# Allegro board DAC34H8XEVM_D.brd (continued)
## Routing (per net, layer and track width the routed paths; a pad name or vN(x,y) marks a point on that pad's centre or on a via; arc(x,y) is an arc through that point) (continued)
N26793352: length 1
  BOTTOM w0.152: R43.2 C34.1
N26794794: length 2
  BOTTOM w0.152: R43.1 C35.1 R133.1
N26951427: length 5.3
  TOP w0.305: T2.4 91.44,60.83 86.36,60.83
N26951636: length 5.3
  TOP w0.305: T9.4 91.44,55.75 T2.6
N26951698: length 5.5
  TOP w0.305: R106.1 R21.2 R22.1 74.37,57.02 73.41,57.99 C265.1 C262.2 L32.1
N26961459: length 5.1
  TOP w0.305: T10.6 91.31,78.74 T3.4
N26961634: length 5.6
  TOP w0.305: R32.2 R34.2
N26961668: length 5.2
  TOP w0.305: R28.1 91.19,73.66 T10.4
N26961730: length 5.6
  TOP w0.305: L35.1 C271.2 C274.1 73.41,75.72 74.32,74.8 R30.1 R29.2 R108.1
N26965899: length 5.6
  TOP w0.305: R110.1 R37.2 R38.1 74.32,87.63 73.41,88.54 C283.1 C280.2 L39.1
N27066000: length 1
  BOTTOM w0.152: R44.2 R45.1
N27118781: length 5.6
  TOP w0.305: L33.1 C265.2 73.41,59.16 74.32,60.07 R100.2 R23.1 R107.1
N27125590: length 5.6
  TOP w0.305: R109.1 R101.2 74.32,77.85 73.41,76.94 C274.2 C277.1 L38.1
N27129848: length 5.6
  TOP w0.305: R111.1 R39.1 R102.2 74.32,90.68 73.41,89.76 C283.2 C286.1 L42.1
N27288441: length 2.6
  BOTTOM w0.152: U3.2 96.45,114.79 R79.2
N27288443: length 24.9
  TOP w0.381: v2(103.61,103.78) 103.84,103.78 105.41,105.36 105.41,111.2 113.14,118.94 v2(113.65,118.94)
  TOP w0.508: J14.2 v2(113.65,118.94)
  BOTTOM w0.381: U3.16 v2(103.61,103.78)
  BOTTOM w0.508: C95.1 111.7,118.94 v2(113.65,118.94)
N27288450: length 16.2
  BOTTOM w0.381: U3.20 101,108.8 102.97,110.77 C92.1
  BOTTOM w0.508: FB14.1 108.64,112.56 C93.1 108.57,110.78 C92.1
N27288471: length 2.8
  BOTTOM w0.152: R80.2 101,114.26 U3.9
N27288510: length 3
  BOTTOM w0.152: U3.10 101.65,113.89 R81.2
N27288614: length 11.9
  TOP w0.152: v2(98.27,114.35) 98.27,114.25 102.95,109.58 v2(102.95,109.47)
  BOTTOM w0.152: v2(102.95,109.47) 102.95,105.22 U3.17 ; v2(98.27,114.35) 98.27,114.55 98.68,114.96 C97.1
N27288630: length 23.1
  TOP w0.381: v2(104.6,106.32) 104.6,112.24 112.04,119.68 113.56,119.68 v2(113.61,119.74)
  TOP w0.508: J14.3 v2(113.61,119.74)
  BOTTOM w0.381: v2(104.6,106.32) 104.25,105.98 U3.15
  BOTTOM w0.508: v2(113.61,119.74) 111.79,119.74 C96.1
N27288689: length 18.7
  TOP w0.152: v2(95.63,116.66) 95.38,116.41 94.39,116.41 94.08,116.71 94.08,117.98 94.74,118.64 95.81,118.64 v2(96.91,119.75) 96.91,119.8 97.16,120.04 97.16,121.26 98.45,122.56 98.7,122.56 100.07,123.92 v2(100.07,128.01)
  BOTTOM w0.152: U4.8 v2(96.91,119.75) ; R75.1 v2(95.63,116.66) ; U9.2 v2(100.07,128.01)
N27288797: length 2.6
  BOTTOM w0.152: R75.2 95.8,114.82 U3.1
N27288876: length 3.1
  BOTTOM w0.152: U3.5 98.4,113.69 R76.2
N27289021: length 2.8
  BOTTOM w0.152: U3.3 97.1,114.42 R77.2
N27289053: length 3.2
  BOTTOM w0.152: R82.2 99.16,113.44 99.16,112.58 U3.6
N27299600: length 3.9
  BOTTOM w0.152: R78.1 104.5,116.74 104.5,118.67 104.32,118.85 U5.9
N27358249: length 5.1
  TOP w0.305: T8.6 T1.4
N27358251: length 5.6
  TOP w0.305: R16.2 R13.2
N27379986: length 5.1
  TOP w0.305: T11.6 91.31,91.69 T4.4
N27396936: length 5.2
  TOP w0.305: R4.1 91.19,43.18 T8.4
N27404153: length 5.1
  TOP w0.305: T4.6 91.31,86.61 T11.4
N27685853: length 1
  TOP w0.305: R99.1 R7.2
N27688076: length 1
  TOP w0.305: 74.42,59.05 R22.2
N27690605: length 1
  TOP w0.305: R101.1 R30.2
N27692844: length 1
  TOP w0.305: R102.1 R38.2
N27760065: length 8.1
  TOP w0.305: U2.29 v2(67.58,112.18) ; v2(67.67,110.06) 67.67,110.21 67.19,110.68 U2.26 ; C76.1 68.25,110.62 v2(68.2,110.67) ; v2(67.46,113.67) 67.44,113.68 U2.32 ; C77.1 v2(68.19,113.67) ; C78.1 v2(68.2,112.29)
  BOTTOM w0.508: FB9.2 v2(68.25,109.88) ; C81.1 67.18,108.79 v2(67.67,109.27) ; v2(67.67,110.06) C79.1 ; C80.1 67.44,111.43 v2(68.2,110.67)
N27760104: length 5.6
  TOP w0.305: U2.47 60.71,117.05 60.49,117.27 60.38,117.27 60.12,117.53 v2(59.97,117.53) 59.6,117.89 C65.1
  BOTTOM w0.508: C66.1 60.55,117.53 v2(59.97,117.53) 59.94,117.55 v2(59.94,118.16) 59.56,118.16 59.05,118.67 FB5.2
N27760106: length 4.7
  TOP w0.152: C64.2 66.62,118.49 65.28,117.14 65.28,116.53 U2.38
N27760178: length 5.2
  TOP w0.508: C180.1 FB25.2 57.02,136.88 59.64,134.26 JP7.1
N27760241: length 4.1
  TOP w0.381: C177.1 R95.1 54.48,123.54 U17.5
N27760265: length 7
  TOP w0.305: J9.1 R49.2 C53.1
N27760429: length 9.8
  TOP w0.152: C75.2 50.95,116.99 51.5,116.45 51.99,116.45 52.67,115.77 54.1,115.77 55.17,114.71 56.07,114.71 56.1,114.73 57.79,114.73 58.33,114.18 U2.4
N27760435: length 4.2
  TOP w0.152: JP4.3 63.14,132.08 R51.2 63.2,132.97 R103.2
N27760437: length 4.3
  TOP w0.305: C86.1 57.69,112.17 v2(57.71,112.19) 57.73,112.17 58.29,112.17 58.27,112.19 58.36,112.19 58.37,112.18 U2.8
  BOTTOM w0.508: C87.1 57.73,112.17 FB12.2 57.3,111.79 v2(57.71,112.19)
N27760441: length 19.5
  TOP w0.152: U2.31 69.81,113.18 70.1,113.48 70.1,115.49 71.2,116.59 71.2,125.78 JP5.2
N27760496: length 4
  TOP w0.305: U2.21 v2(64.21,107.83) C82.1
  BOTTOM w0.508: C83.1 64.21,107.83 v2(64.21,107.83) 64.57,107.47 FB10.2
N27760516: length 3.5
  TOP w0.305: U2.1 58.61,115.68 v2(58.57,115.65) 58.27,115.65 58.19,115.72 v2(57.71,115.72) 57.7,115.73 C73.1
  BOTTOM w0.508: C74.1 v2(58.57,115.65) ; v2(57.71,115.72) 57.71,115.67 57.35,115.32 FB8.2
N27760568: length 10.2
  TOP w0.152: U2.9 59.31,111.56 56.11,111.56 55.68,111.13 54.81,110.26 54.81,109.4 53.98,108.56 53.62,108.56 R61.2
  TOP w0.305: R116.1 R65.1 R61.2
N27760578: length 7.7
  TOP w0.305: C177.2 R167.2 ; R166.2 55.62,115.19 58.12,115.19 58.62,114.68 U2.3
  TOP w0.381: R166.2 R167.2
N27760635: length 11.5
  TOP w0.508: v2(47.42,130) 46.25,131.17 U17.1 46.09,135.22 TP14.1 46.81,135.61 47.96,134.47 R164.2 R165.1
  BOTTOM w0.508: U16.8 48.08,129.34 v2(47.42,130)
N27760767: length 10.2
  TOP w0.152: R60.2 53.54,108.28 54.09,108.28 55.09,109.28 55.09,110.15 55.96,111.01 56.22,111.28 59.34,111.28 U2.10
  TOP w0.305: R117.1 R64.1 R60.2
N27760883: length 4.3
  TOP w0.152: R55.2 70.47,112.75 66.55,112.75 U2.30
N27760967: length 1.2
  TOP w0.152: R48.2 63.58,121.88 C52.2
N27760969: length 20.6
  TOP w0.152: U2.12 v2(59.43,109.63)
  L6_PWR w0.152: v2(59.43,109.63) 59.43,116.84 56.58,119.7 56.58,126.48 JP6.2
N27760997: length 4
  TOP w0.305: C67.1 v2(57.66,114.05) 58.03,113.68 U2.5
  BOTTOM w0.508: C68.1 58,113.72 v2(57.66,114.05) 57.3,113.7 FB6.2
N27761158: length 3.6
  TOP w0.305: U2.18 62.71,107.98 v2(62.71,107.98) 62.43,107.7 C88.1
  BOTTOM w0.508: C89.1 62.69,108 v2(62.71,107.98) 62.71,107.94 62.83,107.83 FB13.1
N27761194: length 1.8
  TOP w0.305: R52.2 69.29,121.31 D1.1
N27761235: length 4.8
  TOP w0.152: U2.37 65.71,116.86 68.02,119.18 R52.1
N27761514: length 5.3
  TOP w0.152: R54.2 54.78,113.33 55.42,113.33 55.63,113.13 56.59,113.13 56.64,113.08 59.33,113.08 U2.6
N27761516: length 5.3
  TOP w0.152: U2.7 59.34,112.78 56.55,112.78 56.48,112.85 55.47,112.85 55.27,113.06 54.8,113.06 R58.2
N27761629: length 3.4
  TOP w0.152: C63.2 58.04,118.47 58.04,118.21 59.79,116.46 U2.48
N27761758: length 3.4
  TOP w0.305: v2(58.37,109.98) 58.37,110.39 58.66,110.68 U2.11 ; v2(57.81,110.19) 57.48,110.52 C84.1
  BOTTOM w0.508: C85.1 v2(57.94,110.72) ; v2(57.3,109.6) FB11.2
N27792689: length 1
  TOP w0.152: C1.2 R149.2
N27792693: length 1
  TOP w0.152: C2.2 R152.2
N27795123: length 1
  TOP w0.152: R125.2 C4.2
N27795145: length 1
  TOP w0.152: R154.2 C3.2
N27836250: length 13
  BOTTOM w1.524: TP12.1 38.07,13.46 JP10.1
  BOTTOM w2.032: 38.07,14.61 46.41,14.61 J18.1
N27836254: length 2.5
  TOP w0.254: D2.1 42.65,27.56 v2(42.65,26.54)
  BOTTOM w0.254: R143.1 v2(42.65,26.54)
N27959634: length 4.9
  TOP w0.305: U11.4 52.84,19.95 52.45,19.56 52.45,17.81 R148.2
  TOP w0.508: 51.56,8.89 FB31.1 ; R148.2 C165.1
  TOP w0.762: C165.1 52.43,15.91 52.48,15.91
N27964126: length 7.3
  TOP w0.305: L25.1 56.26,13.23 56.26,14.48 56.87,15.08 56.87,19.23 56.65,19.45 U11.6
N27965290: length 2.7
  TOP w0.305: U11.5 53.34,17.88 R148.1
  TOP w0.508: R148.1 R151.2
N27972790: length 8.2
  TOP w0.508: R150.2 C166.1 53.44,26.42 C167.1
  TOP w1.016: C167.1 L26.2 57.51,26.04 57.89,26.42 57.89,27.18 FB30.1
N27972794: length 8.6
  TOP w0.305: U11.1 53.34,23.98 52.43,24.89 C166.2 R150.1 R153.2
N28017911: length 2.5
  TOP w0.508: U12.5 64.74,10.26 64.97,10.03 C162.1
N28017929: length 6.5
  TOP w0.762: R147.1 C145.1 63.47,7.49 63.47,7.52 ; C164.1 63.47,7.52 ; 63.47,7.52 U12.4
N28017933: length 9
  TOP w0.762: 59.66,7.37 U12.1 ; U12.2 60.93,8 60.17,7.24
  TOP w1.016: 60.17,7.24 60.05,7.37 R146.2
N28058738: length 11
  TOP w0.305: U13.3 v2(70.53,5.42) ; U13.1 v2(70.53,7.7)
  TOP w0.508: v2(52.68,5.33) C133.1 v2(53.57,4.57) ; C169.1 v2(69.16,5.18) ; v2(58.14,4.6) R146.1 v2(57.25,5.33) ; v2(56.36,4.6) R145.2 v2(55.47,5.33) ; v2(51.41,4.5) FB31.3 v2(50.39,5.33) ; v2(54.97,5.08) C234.1 v2(54.46,5.59) ; v2(73.91,3.56) R126.2 v2(74.65,2.69)
N29123763: length 1.9
  TOP w0.508: T1.5 v2(90.3,45.72)
  BOTTOM w0.508: R9.1 90.27,45.75 v2(90.3,45.72)
N29143306: length 2.1
  TOP w0.508: T2.5 v2(90.25,58.42)
  BOTTOM w0.508: R12.1 90.22,58.45 v2(90.25,58.42)
N29165572: length 2.1
  TOP w0.508: T3.5 v2(90.14,76.33)
  BOTTOM w0.508: R14.1 90.12,76.3 v2(90.14,76.33)
N29179841: length 2.1
  TOP w0.508: T4.5 v2(90.17,89.28)
  BOTTOM w0.508: R18.1 90.14,89.26 v2(90.17,89.28)
N29448574: length 5.6
  TOP w0.305: R40.1 R36.2
N29464199: length 5.6
  TOP w0.305: R20.2 R24.1
N29945616: length 5.4
  BOTTOM w0.102: U1.D12 48.98,70.24 49.36,70.62 49.89,70.62 50.12,70.85 50.12,73.08
  BOTTOM w0.152: R133.2 51.26,73.86 50.88,73.86 50.12,73.11 50.12,73.08
N30016149: length 7
  TOP w0.305: 77.52,5.84 77.44,5.84 77.22,5.61 76.99,5.61 ; 77.52,5.84 77.52,6.78 77.74,7 U22.1 ; 77.52,5.84 77.65,5.84 77.65,5.7 ; 77.65,5.7 U22.3 ; 77.65,5.7 77.58,5.7 77.32,5.44 76.99,5.44 76.99,5.61 ; 76.99,5.61 76.81,5.61 76.68,5.49 C240.1
  TOP w1.016: C240.1 R126.1
N30175128: length 15.9
  TOP w0.508: 74.14,9.78 74.27,9.65 R257.2 73.2,8 72.43,7.22 U13.5 ; FB34.1 70.74,14.77 ; C244.1 70.59,11.46 C245.1 70.74,12.6
  TOP w0.762: C146.1 70.74,9.88 C244.1 70.74,14.77
  TOP w1.016: C146.1 R128.2
N30185572: length 13.1
  TOP w0.508: 80.85,7.72 80.11,8.46 80.11,9.27 C149.1 80.37,9.04 ; 80.85,7.72 81.33,7.72 ; 80.85,7.72 80.71,7.72 80.43,7.44 U22.5 ; 81.69,7.72 80.37,9.04 ; 81.69,7.72 R221.2 ; 81.69,7.72 81.33,7.72 ; 80.37,9.04 80.37,8.69 81.33,7.72 ; C246.1 80.11,11.2 C247.1 80.11,13.34 R127.1
  TOP w0.762: C246.1 80.26,9.63 C149.1
N30679143: length 4.9
  BOTTOM w0.508: 114.17,109.96 U20.5 ; 114.17,109.96 113.66,110.46 v2(113.66,111.05) ; 114.17,109.96 114.05,109.83 v2(113.11,109.83) 112.52,109.83 C138.1 ; R134.1 v2(111.07,107.34) ; R135.2 v2(111.38,110.24)
N30742942: length 2.6
  BOTTOM w0.508: JP11.1 108.08,108.05 R137.2
N30744213: length 2
  BOTTOM w0.508: R136.2 JP11.3
N30812023: length 10.9
  TOP w0.152: v2(100.72,122.18) 100.72,121.3 98.25,118.82 v2(97.71,118.82) 97.71,118.31 99.47,116.56 v2(99.69,116.56)
  BOTTOM w0.152: R76.1 v2(99.69,116.56) ; U9.12 v2(100.72,122.18) ; v2(97.71,118.82) 97.69,118.85 U4.9
N30837851: length 2.1
  BOTTOM w0.152: R85.1 93.71,119.25 U4.5
N30839067: length 1.8
  BOTTOM w0.152: U4.4 R138.1
N30879489: length 2
  BOTTOM w0.152: U5.5 100.56,119.25 R139.1
N30880109: length 1.7
  BOTTOM w0.152: U5.4 R140.1
N30892277: length 5.2
  BOTTOM w0.152: U9.3 100.72,130.37 100.46,130.63 98.91,130.63 R84.1
N30900342: length 20.2
  TOP w0.152: v2(100.89,127.27) 100.89,125.22 102.49,123.62 102.79,123.62 103.86,122.56 103.86,119.51 101.73,117.37 v2(101.73,116.56)
  BOTTOM w0.152: R80.1 v2(101.73,116.56) ; U9.5 102.02,127.8 101.49,127.27 v2(100.89,127.27) 98.36,127.27 97.51,128.12 R74.2
N30908653: length 7.3
  BOTTOM w0.152: R86.1 97.79,126.72 101.68,126.72 102.67,127.72 U9.6
N30910378: length 18.2
  TOP w0.152: v2(99.9,122.15) 99.72,122.15 97.46,119.89 97.46,119.61 96.98,119.13 95.94,118.08 95.94,117.37 v2(96.65,116.66)
  BOTTOM w0.152: R79.1 v2(96.65,116.66) ; v2(99.9,122.15) 100.07,122.32 U9.13 100.07,124.79 99.79,125.07 R83.2 96.93,125.55 96.93,126.44 96.75,126.62 95.15,126.62 94.73,127.04 U10.1
N30914286: length 8.9
  TOP w0.152: v2(103.32,122.37) 103.07,122.12 102.62,122.12 101.65,121.16 101.65,119.28 100.71,118.34 v2(100.71,116.56)
  BOTTOM w0.152: R82.1 v2(100.71,116.56) ; U9.8 v2(103.32,122.37)
N30924628: length 9.9
  BOTTOM w0.152: JP13.2 93.68,131.78 93.68,128.04 93.17,127.53 93.17,126.67 93.75,126.09 U10.2 R87.2
N30955591: length 16.3
  BOTTOM w0.152: R81.1 102.49,116.26 102.49,116.48 102.21,116.76 102.21,116.76 101.24,117.73 100.18,117.73 99.44,118.47 99.44,121.28 98.07,122.66 94.92,122.66 92.44,125.14 U10.4
N30963273: length 12.9
  BOTTOM w0.152: R77.1 97.66,115.93 98.09,115.49 104.34,115.49 105.41,116.56 R73.2 105.39,119.25 U5.8
N30997791: length 4.8
  BOTTOM w0.152: JP9.2 96.39,129.41 R84.2
N30998469: length 6.7
  BOTTOM w0.152: R86.2 95.91,127.1 95.17,127.84 95.17,131.5 JP12.2
N31553936: length 5.5
  BOTTOM w0.152: R87.1 99.62,126.09 101.37,124.33 U9.11
N32018373: length 10
  BOTTOM w0.152: JP8.2 103.99,131.6 103.99,127.51 102.67,126.19 U9.9
N33970284: length 3
  TOP w0.508: U22.4 82.41,5.7 R315.2 R221.1
N33977043: length 2.9
  TOP w0.508: U13.4 74.13,5.83 R316.2 R257.1
N34116776: length 2
  TOP w0.305: C116.1 16.26,106.37 U15.6
N34116835: length 3.2
  TOP w0.305: U15.3 22.76,106.37 22.96,106.17 R170.1 R168.2
N34123238: length 16.1
  TOP w1.016: 76.56,13.59 76.89,13.92 76.89,14.61 ; 76.56,13.59 77.9,13.59 ; 76.56,13.59 76.17,13.97 ; 76.56,13.59 74.78,11.81 74.63,11.96 74.63,12.42 76.17,13.97 ; 76.89,14.61 77.9,13.59 ; 76.89,14.61 76.89,15.35 FB35.1 78.33,14.52 R127.2 77.9,13.59 ; 76.17,16.08 76.17,13.97
N34173216: length 3.8
  TOP w0.305: R105.2 79.88,47.24 T8.1
N34173251: length 3.8
  TOP w0.305: R104.2 79.88,44.2 T8.3
N34173344: length 5.6
  TOP w0.305: L30.1 C259.1 C254.2 73.41,46.41 74.24,47.24 R99.2 R10.1 R105.1
N34173621: length 3.6
  TOP w0.305: 80.77,60.83 80.49,60.83 79.73,60.07 R107.2
N34173656: length 3.8
  TOP w0.305: R106.2 79.27,57.02 80.54,55.75 T9.3
N34174309: length 3.7
  TOP w0.305: T10.1 80.47,78.74 79.58,77.85 R109.2
N34174344: length 3.8
  TOP w0.305: T10.3 80.49,73.66 79.35,74.8 R108.2
N34174546: length 3.7
  TOP w0.305: T11.1 80.54,91.69 79.53,90.68 R111.2
N34174581: length 3.7
  TOP w0.305: T11.3 80.52,86.61 79.5,87.63 R110.2
N34195362: length 2
  TOP w0.305: R131.1 48.67,93.03 U6.19
N34195366: length 4.6
  TOP w0.305: C100.2 51.2,100.25 R206.1 51.07,98.65 49.3,98.65 U6.3
N34195397: length 3.1
  TOP w0.305: R207.1 49.78,100.22 v2(50.13,99.87) 50.48,99.52 R206.2 R207.1
  BOTTOM w0.305: C54.2 v2(50.13,99.87) 49.77,100.23
N34195475: length 4.6
  TOP w0.305: C99.2 49.1,100.99 R207.2 48.92,100.82 48.92,98.98 48.17,98.23 U6.4
N34209596: length 19.7
  TOP w0.305: R122.1 44.7,79.43 43.42,80.71 42.68,80.71 42.4,80.99 42.4,81.36 42.77,81.73 42.77,82.1 42.49,82.37 42.12,82.37 41.75,82.01 41.39,82.01 41.11,82.29 41.11,82.65 41.48,83.02 41.48,83.39 41.2,83.67 40.83,83.67 40.46,83.3 40.09,83.3 39.81,83.58 39.81,83.95 40.18,84.32 40.18,84.68 39.9,84.96 39.54,84.96 39.17,84.59 38.8,84.59 38.18,85.22 38.18,89.79 J20.1
N34209604: length 19.6
  TOP w0.305: R123.1 47.75,79.2 47.19,79.76 47.19,80.16 47.62,80.59 48.26,80.59 50.42,82.75 50.42,83.36 49.94,83.85 49.38,83.85 47.04,81.51 46.41,81.51 45.31,82.6 45.31,83.74 45.62,84.05 46,84.05 46.23,83.82 46.23,83.13 46.58,82.78 47.07,82.78 47.85,83.57 J21.1
N34210478: length 19.6
  TOP w0.305: J22.1 55.83,93.37 55.25,92.79 53.42,92.79 51.31,90.68 51.31,82.58 48.92,80.19 48.92,78.26 R124.1
N34210481: length 19.6
  TOP w0.305: J23.1 56.24,79.96 55.93,79.65 55.32,79.65 54.94,80.04 54.94,83.19 54.61,83.52 53.98,83.52 53.72,83.26 53.72,79.38 53.39,79.04 53.01,79.04 52.76,79.3 52.76,80.01 52.35,80.42 51.92,80.42 51.69,80.19 51.69,78.23 R125.1
N34222239: length 19.9
  TOP w0.305: J10.1 40.51,124.66 50.22,114.96 R121.1
N34226368: length 20
  TOP w0.305: J11.1 38.28,124.76 47.62,115.42 47.62,111.99 48.13,111.48 50.14,111.48 R120.1
N34231598: length 19.9
  TOP w0.305: J12.1 40.59,116.97 41.38,116.18 41.76,116.18 41.84,116.25 42.22,116.25 42.49,115.99 42.49,115.61 41.95,115.07 41.95,114.69 42.22,114.42 42.6,114.42 43.13,114.96 43.51,114.96 43.78,114.69 43.78,114.31 43.24,113.78 43.24,113.4 43.51,113.13 43.89,113.13 43.97,113.21 44.35,113.21 47.57,109.98 R129.1
N34231946: length 20
  TOP w0.305: R130.2 48.54,106.93 46.13,109.35 44.44,109.35 44.17,109.61 44.17,109.82 43.91,110.08 43.53,110.08 43.26,109.82 43.26,108.88 42.99,108.61 42.61,108.61 42.35,108.88 42.35,109.82 42.08,110.08 41.7,110.08 41.43,109.82 41.43,108.88 41.16,108.61 40.78,108.61 40.52,108.88 40.52,109.82 40.25,110.08 39.87,110.08 39.6,109.82 39.6,109.66 39.29,109.35 J15.1
N34233040: length 26.5
  TOP w0.305: J19.1 38.15,101.8 41.3,104.95 53.85,104.95 57.4,108.51 60.45,108.51 60.67,108.73 60.67,108.9 60.71,108.93 U2.14
N34259421: length 3
  TOP w0.305: L28.2 C252.2 C256.1 L27.1
N34259427: length 3
  TOP w0.305: L30.2 C257.1 C256.2 L29.1
N34269055: length 3
  TOP w0.305: L32.2 C260.2 C264.1 L31.1
N34269061: length 3
  TOP w0.305: L33.2 C264.2 L34.1
N34269953: length 3
  TOP w0.305: L36.1 C273.1 C270.2 L35.2
N34269959: length 3
  TOP w0.305: L38.2 C276.1 C273.2 L37.1
N34270526: length 3
  TOP w0.305: L39.2 C279.2 C282.1 L40.1
N34270532: length 3
  TOP w0.305: L41.1 C282.2 C285.1 L42.2
N34315833: length 31.8
  TOP w0.305: v2(49.86,17.55) v2(49.86,18.21) ; v2(49.86,17.55) 49.66,17.35 49,17.35 v2(48.77,17.58) ; v2(49.86,17.55) 49.83,17.58 49.38,17.58 ; v2(49.86,18.21) 49.68,18.03 49.38,18.03 ; v2(49.86,18.21) 49.83,18.24 49.48,18.24 ; 49.38,17.58 v2(48.77,17.58) ; 49.38,17.58 49.38,18.03 ; v2(48.77,17.58) v2(48.77,18.24) ; v2(48.77,17.58) 49.14,17.95 U21.5 ; v2(48.77,18.24) 49.48,18.24 ; v2(48.77,18.24) 49.12,18.59 49.48,18.59 49.48,18.24 ; v2(48.77,18.24) 48.97,18.03 49.38,18.03
  BOTTOM w1.016: 44.83,18.24 v2(48.77,18.24) 48.79,18.21 v2(49.86,18.21) ; 44.83,18.24 45.49,17.58 v2(48.77,17.58) 48.79,17.55 v2(49.86,17.55) ; 44.83,18.24 44.28,18.24 44.27,18.25 ; 44.27,18.25 43.57,18.25 43.57,19.05 44.27,19.05 ; 44.27,18.25 44.27,19.05 ; 44.27,19.05 44.27,19.85
  BOTTOM w1.27: JP10.2 38.46,19.68 43.41,19.68 43.57,19.85 ; 44.27,19.2 44.68,19.2 44.83,19.05 44.83,18.24 ; 43.57,19.85 43.57,19.05 ; 43.57,19.85 44.27,19.85
  vias: v2(40.13,19.56) v2(40.39,20.95) v2(40.51,18.67) v2(40.51,17.68) v2(40.51,17.02) v2(41.78,18.67) v2(41.78,17.68) v2(41.78,17.02)
N34315835: length 31.5
  TOP w0.762: v2(42.65,22.35) v2(42.65,23.11) 42.65,23.49 v2(42.39,23.75) ; v2(42.65,22.35) v2(41.88,22.35) ; v2(42.65,22.35) 42.48,22.19 42.48,22.03 41.88,22.03 v2(41.88,22.35) ; v2(41.88,22.35) v2(41.88,23.11) 41.88,23.37 v2(41.5,23.75) v2(42.39,23.75) ; v2(41.88,22.35) 42.39,22.86 v2(42.39,23.75)
  BOTTOM w0.508: 41.88,23.49 v2(41.88,23.11) ; v2(41.88,23.11) v2(42.65,23.11) ; v2(41.88,23.11) v2(41.88,22.35) ; 40.74,22.73 41.12,22.35 v2(41.88,22.35) ; v2(41.88,22.35) v2(42.65,22.35) ; v2(41.88,22.35) 41.5,22.73 v2(41.5,23.75) v2(42.39,23.75) 42.39,22.61 v2(42.65,22.35) ; v2(42.65,22.35) v2(42.65,23.11) ; v2(42.65,23.11) 42.65,24.26 FB20.2 41.63,25.27 38.93,25.27 C152.1
  BOTTOM w1.016: 40.64,24.68 40.51,24.55 40.51,22.96 40.74,22.73 40.74,24.57 ; 41.88,24.68 41.88,23.49
  BOTTOM w1.524: 40.74,24.57 40.64,24.68 ; 40.64,24.68 42.05,24.68 FB20.2 ; 40.64,24.68 C152.1
N34320644: length 3.6
  TOP w0.381: 44.26,17.02 44.25,17.02 Q3.3
  TOP w0.635: U21.4 46.78,17.95 46.29,17.46 46.29,17.43 45.88,17.02 45.85,17.02 44.26,17.02
N34334652: length 7.1
  TOP w0.152: R157.1 12.52,51.64 12.52,50.11 v1(12.45,50.04)
  BOTTOM w0.152: J13.177 7.71,49.51 7.83,49.63 9.05,49.63 9.33,49.35 11.5,49.35 12.03,49.89 12.29,49.89 v1(12.45,50.04)
N34334661: length 7.1
  TOP w0.152: v1(11.68,51.03) 11.79,51.03 12.24,51.49 12.24,51.66 12.09,51.82 R156.1
  BOTTOM w0.152: J13.175 7.71,50.01 7.81,49.91 9.17,49.91 9.45,49.63 11.38,49.63 11.93,50.18 11.93,50.79 v1(11.68,51.03)
N277617093: length 6.7
  TOP w0.305: R95.2 v2(52.83,120.5)
  BOTTOM w0.305: v2(52.83,120.5) 49.35,123.98 49.35,124.66 U16.5
N279448106: length 5.3
  TOP w0.305: 56.06,21.73 U11.10 56.34,23.34 L26.1 56.46,23.75 56.06,23.34 56.06,21.73

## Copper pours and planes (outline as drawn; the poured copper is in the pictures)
+1.2VCLK on TOP (solid shape): 78.36,27.56 78.36,21.84 78.87,21.84 78.87,20.07 75.56,20.07 75.56,26.8 74.55,27.81 74.55,28.96 75.31,29.72 76.2,29.72
+1.2VCLK on L3_PWR: 72.39,33.91 62.23,44.07 62.23,54.61 51.69,65.15 48.84,65.15 48.39,65.61 48.39,74.3 71.12,74.3 71.12,47.62 81.28,37.47 81.28,18.41 72.39,18.41
+1.2VD on TOP (solid shape): 58.93,31.88 58.93,30.48 54.48,30.48 54.48,30.99 52.83,30.99 52.2,30.35 50.67,30.35 50.55,30.48 49.53,30.48 48.77,31.24 48.77,32.26 49.4,32.89 57.91,32.89
+1.2VD on L3_PWR: 45.72,58.8 47.37,60.45 47.37,61.06 45.39,63.04 45.39,69.67 43.08,69.67 43.08,67.72 41.02,65.66 39.24,65.66 36.2,62.61 36.2,29.84 57.79,29.84 57.79,30.48 48.9,39.37 45.72,39.37
+1.2VDAC on TOP (solid shape): 68.96,24 68.96,21.21 69.22,20.95 70.99,20.95 70.99,19.05 67.56,19.05 67.06,19.56 66.04,19.56 66.04,23.37 64.77,24.64 64.77,25.65 65.53,26.42 66.55,26.42
+1.2VDAC on L3_PWR: 46.1,70.61 46.1,63.5 47.62,61.98 47.62,55.88 52.07,51.44 52.07,40.64 62.87,29.84 62.87,18.41 69.85,18.41 69.85,32.97 60.33,42.49 60.33,54.61 50.8,64.14 48.9,64.14 47.75,65.28 47.75,70.61
+3.3V_LOGIC on L3_PWR: 81.41,137.16 81.41,116.2 120.65,116.2 120.65,137.16
+3.3VA on BOTTOM (solid shape): 60.33,67.67 58.52,67.67 58.52,68.94 60.33,68.94
+3.3VA on L6_PWR: 73.03,2.54 73.03,68.96 52.96,68.96 52.32,69.6 48.13,69.6 47.62,70.1 47.62,70.74 46.36,70.74 46.36,62.87 47.62,61.59 47.62,59.05 46.99,58.42 46.99,40.64 48.9,40.64 58.42,31.11 58.42,17.14 54.61,17.14 54.61,2.54
+3.3VCLK on L3_PWR: 20.32,92.08 20.32,112.39 31.75,112.39 31.75,137.16 78.74,137.16 78.74,116.84 53.98,92.08
+3.3VD on L6_PWR: 43,62.97 39.37,59.33 39.37,33.66 45.47,33.66 45.47,70.74 42.04,70.74 42.04,67.13 43,66.17
GNDA on TOP (solid shape): 68.28,134.11 65.1,134.11 65.1,139.7 68.28,139.7
GNDA on TOP (solid shape): 73.48,134.11 70.31,134.11 70.31,139.7 73.48,139.7
GNDA on TOP (solid shape): 97.64,91.21 96.93,91.21 95.94,90.22 95,90.22 95,90.93 95.63,90.93 95.89,91.19 95.89,92.43 97.64,92.43
GNDA on TOP (solid shape): 97.76,60.35 97.05,60.35 96.06,59.36 95.12,59.36 95.12,60.07 95.76,60.07 96.01,60.33 96.01,61.57 97.76,61.57
GNDA on TOP (solid shape): 96.93,74.4 97.61,74.4 97.64,74.37 97.64,73.18 95.89,73.18 95.89,74.42 95.63,74.68 95,74.68 95,75.39 95.94,75.39
GNDA on TOP (solid shape): 97.05,43.79 97.74,43.79 97.76,43.76 97.76,42.57 96.01,42.57 96.01,43.82 95.76,44.07 95.12,44.07 95.12,44.78 96.06,44.78
GNDA on TOP: 7.87,115.32 29.46,115.32 29.46,139.32 122.94,139.32 122.94,0.25 29.46,0.25 29.46,37.08 7.62,37.08 0.51,44.2 0.51,107.95 ; 23 cut-outs
GNDA on BOTTOM: 7.87,115.32 29.46,115.32 29.46,139.45 122.94,139.45 122.94,0.25 29.46,0.25 29.46,37.08 7.62,37.08 0.57,44.13 0.57,108.01 ; 13 cut-outs
GNDA on L2_GND: 7.87,115.32 29.46,115.32 29.46,139.32 122.94,139.32 122.94,0.25 29.46,0.25 29.46,37.08 7.62,37.08 0.51,44.2 0.51,107.95
GNDA on L3_PWR: 81.92,0.25 81.92,38.1 71.75,48.26 71.75,74.93 47.62,74.93 47.62,73.66 8.26,73.66 8.26,54.86 16.13,54.86 20.32,59.05 35.56,59.05 35.56,28.07 29.46,28.07 29.46,37.08 7.62,37.08 0.51,44.2 0.51,107.95 7.87,115.32 19.69,115.32 19.69,91.44 54.61,91.44 78.74,115.57 104.78,115.57 104.78,102.23 122.94,102.23 122.94,0.25
GNDA on L4_GND: 7.75,115.19 29.59,115.19 29.59,139.32 122.94,139.32 122.94,0.25 29.46,0.25 29.46,37.08 7.62,37.08 0.51,44.2 0.51,107.95
GNDA on L5_GND, L7_GND: 7.87,115.32 29.46,115.32 29.46,139.45 122.94,139.45 122.94,0.25 29.46,0.25 29.46,37.08 7.62,37.08 0.51,44.2 0.51,107.95
GNDA on L6_PWR: 29.46,0.25 29.46,37.08 7.62,37.08 0.51,44.2 0.51,107.95 7.87,115.32 29.46,115.32 29.46,139.45 122.94,139.45 122.94,0.25 73.66,0.25 73.66,74.93 52.07,74.93 52.07,75.56 79.38,102.87 114.94,102.87 114.94,130.17 85.72,130.17 85.72,119.38 45.72,79.38 14.61,79.38 11.18,75.95 11.18,51.31 13.34,51.31 13.34,67.95 20.57,60.71 38.73,60.71 38.73,33.02 46.36,33.02 46.36,39.37 48.9,39.37 57.79,30.48 57.79,17.78 53.98,17.78 53.98,0.25
VCC on L3_PWR: 31.75,27.3 31.75,19.05 59.06,19.05 59.06,27.3
VCC_VCO on L6_PWR: 65.66,114.3 70.1,114.3 70.1,120.02 65.66,120.02
VDD1 on L6_PWR: 40.01,97.16 40.01,90.17 48.9,90.17 48.9,97.16
A2OUT on TOP (solid shape): 96.93,87.35 97.61,87.35 97.64,87.33 97.64,86.13 95.89,86.13 95.89,87.38 95.63,87.63 95,87.63 95,88.34 95.94,88.34
B2OUT on TOP (solid shape): 97.64,78.26 96.93,78.26 95.94,77.27 95,77.27 95,77.98 95.63,77.98 95.89,78.23 95.89,79.48 97.64,79.48
C2OUT on TOP (solid shape): 97.05,56.49 97.74,56.49 97.76,56.46 97.76,55.27 96.01,55.27 96.01,56.52 95.76,56.77 95.12,56.77 95.12,57.48 96.06,57.48
D2OUT on TOP (solid shape): 97.76,47.65 97.05,47.65 96.06,46.66 95.12,46.66 95.12,47.37 95.76,47.37 96.01,47.62 96.01,48.87 97.76,48.87
GC_+6.0VDC on BOTTOM: 13.23,103.07 13.23,105.77 14.53,105.77 14.53,103.07
IO_LOGIC on L6_PWR: 86.36,129.54 114.3,129.54 114.3,103.5 79.38,103.5 52.22,76.35 47.62,76.35 47.62,80.64 86.36,119.38
Net_284 on TOP (solid shape): 97.08,76.94 97.08,76.71 97.66,76.71 97.66,75.95 97.18,75.95 97.18,75.69 96.14,75.69 95.89,75.95 95,75.95 95,76.71 95.89,76.71 96.14,76.96 97.05,76.96
Net_285 on TOP (solid shape): 97.08,89.89 97.08,89.66 97.66,89.66 97.66,88.9 97.18,88.9 97.18,88.65 96.14,88.65 95.89,88.9 95,88.9 95,89.66 95.89,89.66 96.14,89.92 97.05,89.92
Net_286 on TOP (solid shape): 97.21,46.33 97.21,46.1 97.79,46.1 97.79,45.34 97.31,45.34 97.31,45.09 96.27,45.09 96.01,45.34 95.12,45.34 95.12,46.1 96.01,46.1 96.27,46.36 97.18,46.36
Net_327 on TOP (solid shape): 97.21,59.03 97.21,58.8 97.79,58.8 97.79,58.04 97.31,58.04 97.31,57.79 96.27,57.79 96.01,58.04 95.12,58.04 95.12,58.8 96.01,58.8 96.27,59.05 97.18,59.05
Net_334 on TOP (solid shape): 81.92,58.67 82.8,58.67 82.8,57.91 81.92,57.91 81.66,57.66 80.75,57.66 80.72,57.68 80.72,57.91 80.14,57.91 80.14,58.67 80.62,58.67 80.62,58.93 81.66,58.93
Net_335 on TOP (solid shape): 85.65,58.67 87,58.67 87,57.91 85.65,57.91 85.65,57.66 85.47,57.66 85.22,57.91 84.33,57.91 84.33,58.67 85.22,58.67 85.47,58.93 85.65,58.93
Net_336 on TOP (solid shape): 82.04,46.1 82.93,46.1 82.93,45.34 82.04,45.34 81.79,45.09 80.87,45.09 80.85,45.11 80.85,45.34 80.26,45.34 80.26,46.1 80.75,46.1 80.75,46.36 81.79,46.36
Net_337 on TOP (solid shape): 85.78,46.1 87.12,46.1 87.12,45.34 85.78,45.34 85.78,45.09 85.6,45.09 85.34,45.34 84.46,45.34 84.46,46.1 85.34,46.1 85.6,46.36 85.78,46.36
Net_338 on TOP (solid shape): 81.92,89.53 82.8,89.53 82.8,88.77 81.92,88.77 81.66,88.52 80.75,88.52 80.72,88.54 80.72,88.77 80.14,88.77 80.14,89.53 80.62,89.53 80.62,89.79 81.66,89.79
Net_339 on TOP (solid shape): 85.65,89.53 87,89.53 87,88.77 85.65,88.77 85.65,88.52 85.47,88.52 85.22,88.77 84.33,88.77 84.33,89.53 85.22,89.53 85.47,89.79 85.65,89.79
Net_340 on TOP (solid shape): 81.92,76.58 82.8,76.58 82.8,75.82 81.92,75.82 81.66,75.56 80.75,75.56 80.72,75.59 80.72,75.82 80.14,75.82 80.14,76.58 80.62,76.58 80.62,76.84 81.66,76.84
Net_341 on TOP (solid shape): 85.65,76.58 87,76.58 87,75.82 85.65,75.82 85.65,75.56 85.47,75.56 85.22,75.82 84.33,75.82 84.33,76.58 85.22,76.58 85.47,76.84 85.65,76.84
PLLAVDD on BOTTOM (solid shape): 60.15,69.77 58.7,69.77 58.7,70.79 60.15,70.79
PLLAVDD on L6_PWR: 47.88,70.23 47.88,71.25 46.99,72.14 46.99,74.42 73.03,74.42 73.03,69.72 54.1,69.72 53.34,70.48 49.53,70.48 49.02,69.98 48.13,69.98
N26951427 on TOP (solid shape): 87,60.2 86.23,60.2 85.27,59.23 84.33,59.23 84.33,59.94 84.96,59.94 85.22,60.2 85.22,61.44 87,61.44
N26951427 on TOP (solid shape): 92.41,61.57 92.71,61.57 92.71,60.33 92.96,60.07 93.6,60.07 93.6,59.36 92.66,59.36 91.69,60.33 90.93,60.33 90.93,61.59 92.38,61.59
N26951636 on TOP (solid shape): 93.6,56.77 92.96,56.77 92.71,56.52 92.71,55.27 90.93,55.27 90.93,56.52 91.69,56.52 92.66,57.48 93.6,57.48
N26951636 on TOP (solid shape): 86.23,56.39 87,56.39 87,55.12 85.55,55.12 85.52,55.14 85.22,55.14 85.22,56.39 84.96,56.64 84.33,56.64 84.33,57.35 85.27,57.35
N26961459 on TOP (solid shape): 87,78.11 86.23,78.11 85.27,77.14 84.33,77.14 84.33,77.85 84.96,77.85 85.22,78.11 85.22,79.35 87,79.35
N26961459 on TOP (solid shape): 92.28,79.48 92.58,79.48 92.58,78.23 92.84,77.98 93.47,77.98 93.47,77.27 92.53,77.27 91.57,78.23 90.81,78.23 90.81,79.5 92.25,79.5
N26961668 on TOP (solid shape): 93.47,74.68 92.84,74.68 92.58,74.42 92.58,73.18 90.81,73.18 90.81,74.42 91.57,74.42 92.53,75.39 93.47,75.39
N26961668 on TOP (solid shape): 86.23,74.3 87,74.3 87,73.03 85.55,73.03 85.52,73.05 85.22,73.05 85.22,74.3 84.96,74.55 84.33,74.55 84.33,75.26 85.27,75.26
N27358249 on TOP (solid shape): 87.12,47.62 86.36,47.62 85.39,46.66 84.46,46.66 84.46,47.37 85.09,47.37 85.34,47.62 85.34,48.87 87.12,48.87
N27358249 on TOP (solid shape): 92.41,48.87 92.71,48.87 92.71,47.62 92.96,47.37 93.6,47.37 93.6,46.66 92.66,46.66 91.69,47.62 90.93,47.62 90.93,48.9 92.38,48.9
N27379986 on TOP (solid shape): 87,91.06 86.23,91.06 85.27,90.09 84.33,90.09 84.33,90.81 84.96,90.81 85.22,91.06 85.22,92.3 87,92.3
N27379986 on TOP (solid shape): 92.28,92.43 92.58,92.43 92.58,91.19 92.84,90.93 93.47,90.93 93.47,90.22 92.53,90.22 91.57,91.19 90.81,91.19 90.81,92.46 92.25,92.46
N27396936 on TOP (solid shape): 93.6,44.07 92.96,44.07 92.71,43.82 92.71,42.57 90.93,42.57 90.93,43.82 91.69,43.82 92.66,44.78 93.6,44.78
N27396936 on TOP (solid shape): 86.36,43.82 87.12,43.82 87.12,42.55 85.67,42.55 85.65,42.57 85.34,42.57 85.34,43.82 85.09,44.07 84.46,44.07 84.46,44.78 85.39,44.78
N27404153 on TOP (solid shape): 93.47,87.63 92.84,87.63 92.58,87.38 92.58,86.13 90.81,86.13 90.81,87.38 91.57,87.38 92.53,88.34 93.47,88.34
N27404153 on TOP (solid shape): 86.23,87.25 87,87.25 87,85.98 85.55,85.98 85.52,86 85.22,86 85.22,87.25 84.96,87.5 84.33,87.5 84.33,88.21 85.27,88.21
N27760065 on L6_PWR: 65.41,113.92 65.41,108.33 69.22,108.33 69.22,113.92
N27761758 on L6_PWR: 56.95,111.76 56.95,107.95 58.9,107.95 58.9,111.76
N27959634 on TOP (solid shape): 52.7,18.67 52.7,16.89 53.09,16.89 53.09,15.88 54.36,14.61 54.36,13.97 53.85,13.97 53.85,11.94 54.36,11.94 54.36,11.3 52.2,9.14 52.2,8.38 50.55,8.38 50.55,9.4 52.83,11.68 52.83,14.35 51.82,15.37 51.82,16.89 52.2,16.89 52.21,18.67 52.32,19.05 52.58,19.05
N27964126 on TOP (solid shape): 57.4,18.54 57.4,14.73 56.77,14.1 56.77,11.3 55.25,11.3 55.25,11.94 55.75,11.94 55.75,13.97 55.25,13.97 55.25,14.61 56.13,14.61 56.77,15.24 56.77,18.92 57.02,18.92
N28058738 on L3_PWR: 31.75,15.88 31.75,2.54 81.28,2.54 81.28,15.88
N29123763 on TOP (solid shape): 92.71,46.1 93.6,46.1 93.6,45.34 92.71,45.34 92.46,45.09 92.28,45.09 92.28,45.34 90.93,45.34 90.93,46.1 92.28,46.1 92.28,46.36 92.46,46.36
N29143306 on TOP (solid shape): 92.71,58.8 93.6,58.8 93.6,58.04 92.71,58.04 92.46,57.79 92.28,57.79 92.28,58.04 90.93,58.04 90.93,58.8 92.28,58.8 92.28,59.05 92.46,59.05
N29165572 on TOP (solid shape): 92.58,76.71 93.47,76.71 93.47,75.95 92.58,75.95 92.33,75.69 92.15,75.69 92.15,75.95 90.81,75.95 90.81,76.71 92.15,76.71 92.15,76.96 92.33,76.96
N29179841 on TOP (solid shape): 92.58,89.66 93.47,89.66 93.47,88.9 92.58,88.9 92.33,88.65 92.15,88.65 92.15,88.9 90.81,88.9 90.81,89.66 92.15,89.66 92.15,89.92 92.33,89.92
N30175128 on TOP (solid shape): 71.12,10.41 75.44,10.41 75.44,9.14 74.55,9.14 74.55,7.75 73.41,7.75 72.9,7.24 72.9,6.86 72.01,6.86 72.01,7.24 73.03,8.26 74.04,8.26 74.04,9.14 70.23,9.14 70.23,13.97 67.69,13.97 67.69,15.62 71.12,15.62
N30185572 on TOP (solid shape): 80.9,8.89 81.79,8 82.68,8 82.68,7.49 81.53,7.49 80.9,6.86 80.01,6.86 80.01,8.13 79.76,8.38 79.76,14.22 80.9,14.22
N30679143 on L3_PWR: 105.41,113.67 105.41,102.87 120.65,102.87 120.65,113.67
N34123238 on TOP (solid shape): 78.87,12.95 76.71,12.95 75.44,11.68 75.44,11.3 74.04,11.3 74.04,12.7 75.56,14.22 75.56,16.64 78.87,16.64
N34173216 on TOP (solid shape): 82.04,47.62 82.3,47.37 82.93,47.37 82.93,46.66 81.99,46.66 81,47.65 80.31,47.65 80.29,47.68 80.29,48.87 82.04,48.87
N34173251 on TOP (solid shape): 82.93,44.07 82.3,44.07 82.04,43.82 82.04,42.57 80.29,42.57 80.29,43.79 81,43.79 81.99,44.78 82.93,44.78
N34173621 on TOP (solid shape): 81.92,60.2 82.17,59.94 82.8,59.94 82.8,59.23 81.86,59.23 80.87,60.22 80.19,60.22 80.16,60.25 80.16,61.44 81.92,61.44
N34173656 on TOP (solid shape): 82.8,56.64 82.17,56.64 81.92,56.39 81.92,55.14 80.16,55.14 80.16,56.36 80.87,56.36 81.86,57.35 82.8,57.35
N34174309 on TOP (solid shape): 81.92,78.11 82.17,77.85 82.8,77.85 82.8,77.14 81.86,77.14 80.87,78.13 80.19,78.13 80.16,78.16 80.16,79.35 81.92,79.35
N34174344 on TOP (solid shape): 82.8,74.55 82.17,74.55 81.92,74.3 81.92,73.05 80.16,73.05 80.16,74.27 80.87,74.27 81.86,75.26 82.8,75.26
N34174546 on TOP (solid shape): 81.92,91.06 82.17,90.81 82.8,90.81 82.8,90.09 81.86,90.09 80.87,91.08 80.19,91.08 80.16,91.11 80.16,92.3 81.92,92.3
N34174581 on TOP (solid shape): 82.8,87.5 82.17,87.5 81.92,87.25 81.92,86 80.16,86 80.16,87.22 80.87,87.22 81.86,88.21 82.8,88.21
N34315833 on TOP: 40.01,16.64 40.01,18.16 36.58,18.16 36.58,20.45 40.01,20.45 40.01,21.34 42.29,21.34 42.29,19.05 43.69,19.05 43.69,16.64
N34315835 on TOP: 41.53,22.48 41.53,21.72 44.07,21.72 44.07,17.65 45.59,17.65 45.59,22.48

Small or netless copper shapes (teardrops, artwork), in the pictures only: 3 on BOTTOM

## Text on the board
BOTTOM: LAYER 8 (BOTTOM SIDE)
Ref Des/Assembly Bottom: BOTTOM SIDE
Board Geometry/Soldermask Bottom: SOLDERMASK BOTTOM
Ref Des/Silkscreen Bottom: SILKSCREEN BOTTOM
User.Comments: TEXAS INSTRUMENTS | DAC34H8X EVM REV D
TOP: LAYER 1 (TOP SIDE)
Board Geometry/Soldermask Top: SOLDERMASK TOP
Ref Des/Silkscreen Top: GND | TEST | MODE | +3.3V | CLK | CDC-IO2 | SYNC | CDC-IO2\ | DIGVDD | AVDD | DACVDD | CLKVDD | IOLOGIC | EXTIO | ALARM | IOUTB1 | IOUTC1 | IOUTD1 | IOUTA1 | CDC-IO1 | CDC-IO1\ | CLKIN | DAC34H84 EVM | DAC34SH84 EVM | REV D | +6V | IN | PLLAVDD | IOUTB2 | IOUTD2 | IOUTC2 | IOUTA2 | J13 | SILKSCREEN TOP
L2_GND: LAYER 2 - GND
L3_PWR: LAYER 3 - POWER
L4_GND: LAYER 4 - GND
L5_GND: LAYER 5 - GND
L6_PWR: LAYER 6 - POWER
L7_GND: LAYER 7 - GND
DIMENSION: 2 PLC'S
DISPLAY_TOP: PASTEMASK TOP
PASTEMASK_BOTTOM: PASTEMASK BOTTOM
User.9: 2.  FINISHED BOARD SHALL BE RoHS COMPLIANT AND LEAD FREE ASSEMBLY.
User.10: 20. FINISHED BOARDS MUST BE RoHS COMPLIANT AND SURVIVE A LEAD FREE ASSEMBLY, MAXIMUM REFLOW TEMPERATURE OF 260 DEGREE C (6 PASSES). | 18  HOLES SIZE APPLIES AFTER PLATING.  TOLERANCE TO BE +.003/-.010. | 19. FILL VIAS UNDER BGA WITH NON CONDUCTIVE MATERIAL. | 18
User.18: FIGURE | SIZE | 8.0 | 10.0 | 12.0 | 13.0 | 15.0 | 35.0 | 38.0 | 40.0 | 45.0 | 62.0 | 67.0 | 68.0 | 120.0 | 140.0 | 125.0 | DRILL CHART: TOP to BOTTOM | ALL UNITS ARE IN MILS | PLATED | NON-PLATED | QTY | 196 | 1712 | 17 | 9 | 72 | 4 | 1 | 10 | 18 | 26 | 32 | 2 | 6
User.21: C39 | C10 | C51 | C21 | C13 | C20 | C23 | C14 | C17 | C8 | C18 | C138 | R134 | C136 | C137 | FB14 | C93 | C91 | C96 | C95 | R135 | R136 | C92 | R137 | R73 | R78 | C140 | R80 | C141 | R139 | R140 | R77 | C94 | R84 | R74 | R86 | R83 | R87 | C142 | R75 | C139 | R14 | R18 | R12 | R9 | R85 | C98 | R138 | R46 | C47 | FB24 | C72 | FB9 | FB7 | C80 | C79 | C71 | C81 | C60 | C83 | C59 | C61 | C68 | C89 | C87 | C66 | C85 | C74 | R133 | C35 | C34 | C11 | C6 | C15 | C5 | C38 | R43 | C12 | C16 | C9 | C155 | FB20 | R143 | FB22 | C33 | C43 | C154 | C45 | C44 | C31 | C26 | C42 | C41 | C152 | C104 | C54 | C102 | R70 | FB15 | C103 | C62 | R81 | R82 | R76 | C97 | R79 | C48 | C49 | C7 | C19 | C46 | C153 | J13 | 180 | 2 | 179 | 1 | U20 | U5 | U9 | U3 | U4 | U10 | FB4 | FB10 | C40 | FB13 | FB3 | FB1 | C128 | FB5 | FB8 | FB6 | FB11 | FB12 | C24 | C22 | U16 | R44 | R45 | J18 | C28 | C30 | C27 | C29 | 60 | 62 | 120 | 122 | 59 | 61 | 119 | 121 | BOTTOM SIDE
